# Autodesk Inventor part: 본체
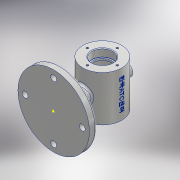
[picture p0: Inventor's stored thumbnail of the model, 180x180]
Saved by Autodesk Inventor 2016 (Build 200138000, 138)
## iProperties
Created: 2018-12
Part Number: 본체
Material: 알루미늄 6061
Document SubType Name: Modeling
Designer: 605-11
Density: 2.7 g/cm^3
Appearance: 알루미늄 - 평지
Mass: 685.082 g
Surface Area: 555.474 cm^2
Volume: 253.734 cm^3
Author: 605-11
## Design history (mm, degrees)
sketch "스케치8"
  geometry: C1 r 55 at (0, 0); 1 further point
  constraints: 1 centre point, 1 coincident
  dimensions: "d5" = 110 diameter of C1
extrude "돌출2" new body sketch "스케치8" distance "d6" = 11; taper "d7" = 0 deg
sketch "스케치9"
  geometry: L1 (55, 11)-(-55, 11) reference; L2 (-55, 11)-(0, 25.737); L3 (0, 11)-(0, 25.737); L4 (-55, 11)-(0, 11); 2 further points
  constraints: 6 end point, 1 midpoint, 1 point on line, 1 vertical
  dimensions: "d8" = 15 deg angle of L1 L2
revolve "회전1" sketch "스케치9" stored, may be unused: angle "d9" = 360 deg
sketch "스케치10"
  geometry: 1 further point
sketch "스케치12"
  geometry: C1 r 30 at (0, 75); 1 further point
  constraints: 1 centre point
  dimensions: "d13" = 60 diameter of C1; "d14" = 75 distance of point (0, 0) C1.centre
extrude "돌출4" join sketch "스케치12" stored distance "d15" = 70; taper "d16" = 0 deg
sketch "스케치11"
  geometry: C1 r 12 at (0, 0); 1 further point
  constraints: 1 centre point, 1 coincident
  dimensions: "d10" = 24 diameter of C1
extrude "돌출3" join sketch "스케치11" stored distance "d11" = 40; taper "d12" = 0 deg
sketch "스케치13"
  geometry: L1 (105, 35)-(45, 35) reference; L2 (75, 35)-(91, 35); L3 (91, 35)-(91, 23); L4 (91, 23)-(75, 23); L5 (75, 23)-(75, 35); L6 (75, 23)-(89, 23); L7 (89, 23)-(89, 20); L8 (89, 20)-(75, 20); L9 (75, 20)-(75, 23); L10 (75, 20)-(100, 20); L11 (100, 20)-(100, -20); L12 (100, -20)-(75, -20); L13 (75, -20)-(75, 20); 1 further point
  constraints: 24 end point, 6 parallel, 3 horizontal, 3 perpendicular, 1 midpoint
  dimensions: "d17" = 32 diameter of L3 L5; "d18" = 28 diameter of L7 L9; "d19" = 50 diameter of L11 L13; "d20" = 12 distance between parallel lines of L4 L1; "d21" = 3 distance between parallel lines of L8 L4; "d22" = 40 distance between parallel lines of L10 L12
revolve "회전2" sketch "스케치13" stored, may be unused: angle "d23" = 360 deg
node "작업 평면1"
sketch "스케치14"
  geometry: C1 r 10 at (0, 0); 1 further point
  constraints: 1 centre point, 1 coincident
  dimensions: "d25" = 20 diameter of C1
extrude "돌출5" join sketch "스케치14" stored distance "d26" = 70; taper "d27" = 0 deg
sketch "스케치15"
  geometry: C1 r 10 at (0, 0) reference; C2 r 5 at (0, 0)
  constraints: 1 centre point, 1 coincident
  dimensions: "d28" = 10 diameter of C2
extrude "돌출6" cut sketch "스케치15" stored distance "d29" = 0; taper "d30" = 0 deg
sketch "스케치17" dims "d31" = 46
  geometry: C1 r 30 at (0, 0) reference; 3 further points
  constraints: 1 coincident, 1 vertical alignment, 2 other
hole "구멍1" sketch "스케치17" at (0, 23) diameter "d32" = 3.242; stored, may be unused: countersink angle "d36" = 90 deg, drill point angle "d38" = 118 deg; dims "d33" = 8, "d34" = 4, "d35" = 2, "d37" = 10
sketch "스케치18" dims "d42" = 88
  geometry: C1 r 4.5 at (44, 0); 2 further points
  constraints: 1 centre point, 1 coincident, 1 horizontal alignment, 2 other
  dimensions: "d43" = 9 diameter of C1
extrude "돌출7" cut sketch "스케치18" stored distance "d44" = 70; taper "d45" = 0 deg
node "작업 평면2"
sketch "스케치19"
  geometry: C1 r 4.5 at (44, 0) reference; C2 r 7 at (44, 0); 1 further point
  constraints: 1 centre point, 1 coincident
  dimensions: "d47" = 14 diameter of C2
extrude "돌출8" cut sketch "스케치19" distance "d48" = 10; taper "d49" = 0 deg
fillet "모깎기1" dims "d53" = 3
fillet "모깎기2" dims "d54" = 0.3
chamfer "모따기1" distance "d55" = 1; stored, may be unused: second distance "d56" = 2, angle "d57" = 45 deg
sketch "스케치22"
  geometry: L1 (105, 35)-(45, 35) reference; 2 further points
  constraints: 1 other
  dimensions: "d58" = 35 distance from line of L1 point (75, 0); "d59" = 30 horizontal distance of L1.start point (75, 0)
feature "엠보싱1" sketch "스케치22" dims "d60" = 0.5, "d61" = 0
node "솔리드2"
mirror "대칭1"
pattern_circular "원형 패턴1" dims angle "d40" = 360 deg
mirror "대칭2"
pattern_circular "원형 패턴2" dims angle "d51" = 360 deg
other parameters: "d24" = 112
